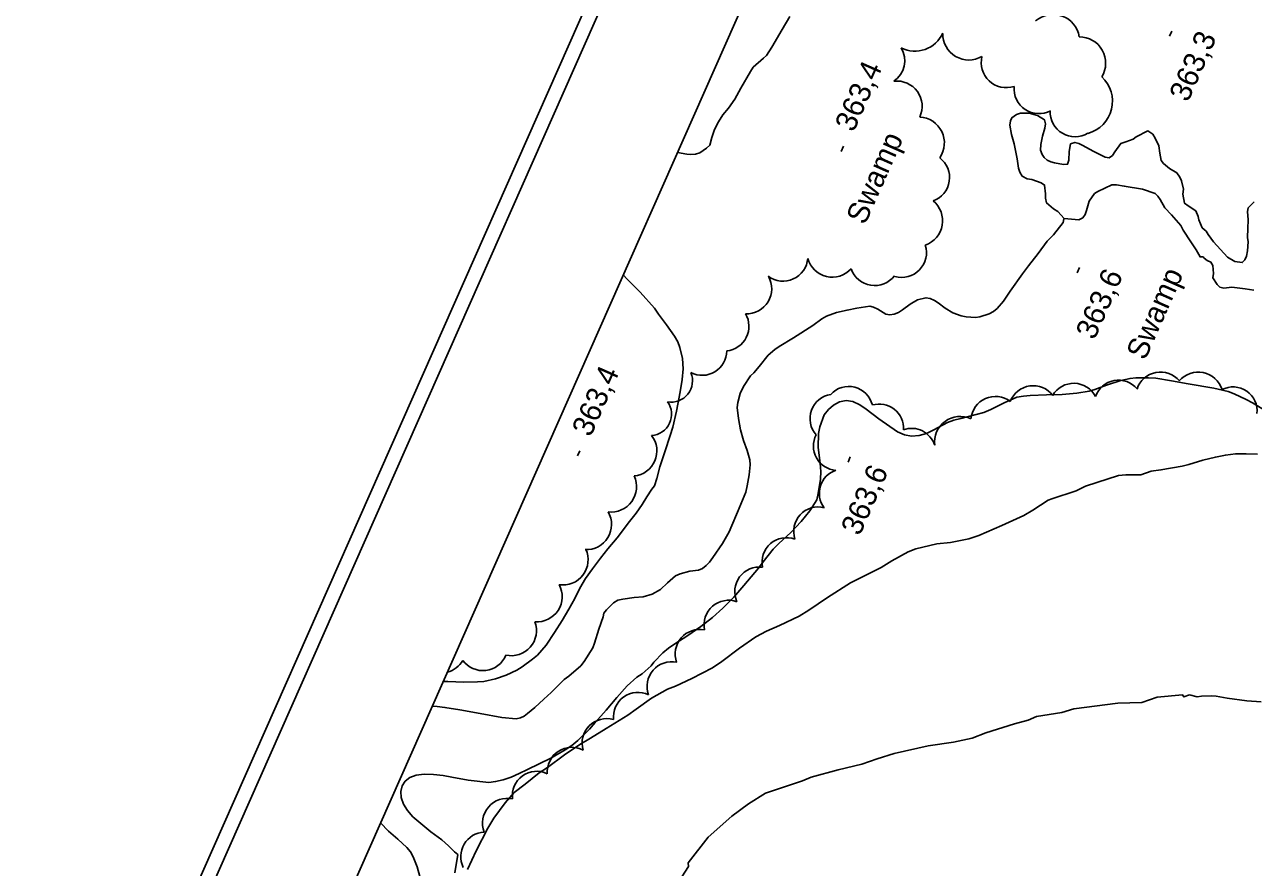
# Model space of a CAD drawing. Extents: x 287698 to 290158, y 5234163 to 5237182.
# Drawn here: x 288054.4 to 288226.3, y 5235640.4 to 5235758.4 of the extents above; entities that cross this region are included whole.
import ezdxf

# ---------------------------------------------------------------- set-up
doc = ezdxf.new("R2010")
doc.units = 0
for name, color, linetype in [('Niveau 2', 7, 'Continuous'), ('Niveau 3', 7, 'Continuous'), ('Niveau 4', 7, 'Continuous'), ('Niveau 44', 7, 'Continuous'), ('Niveau 60', 7, 'Continuous'), ('Niveau 7', 7, 'Continuous')]:
    doc.layers.add(name, color=color, linetype=linetype)

msp = doc.modelspace()

# ---------------------------------------------------------------- linework, layer by layer
at = {"layer": 'Niveau 2'}
for points in [[(288210.56, 5235695.35), (288212.02, 5235695.86), (288213.37, 5235696.06), (288216.33, 5235696.57), (288217.29, 5235696.83), (288219.23, 5235697.4), (288221, 5235697.86), (288222.41, 5235698.13), (288223.82, 5235698.3), (288225.32, 5235698.31), (288226.87, 5235698.26)], [(288179.08, 5235685.01), (288182.04, 5235685.7), (288183.93, 5235685.91), (288186.53, 5235686.4), (288187.93, 5235686.9), (288191.11, 5235688.27), (288194.19, 5235689.69), (288195.48, 5235690.43), (288197.63, 5235691.83), (288198.14, 5235692.02), (288201.54, 5235693.15), (288202.82, 5235693.76), (288204.41, 5235694.28), (288207.46, 5235695.27), (288208.47, 5235695.38), (288210.56, 5235695.35)], [(288116.37, 5235640.14), (288117.59, 5235642.77), (288119.22, 5235645.94), (288120.07, 5235647.3), (288121.66, 5235649.46), (288122.92, 5235650.92), (288124.43, 5235652.06), (288126.4, 5235653.67), (288127.58, 5235654.39), (288129.97, 5235656.18), (288132.08, 5235657.64), (288133.57, 5235658.53), (288135.77, 5235659.88), (288138.82, 5235661.72), (288139.97, 5235662.56), (288142.12, 5235664.13), (288144.38, 5235665.36), (288145.46, 5235665.8), (288147.78, 5235666.89), (288150.64, 5235668.36), (288151.97, 5235669.24), (288154.42, 5235671.1), (288156.71, 5235672.7), (288158.2, 5235673.51), (288160.01, 5235674.27), (288162.76, 5235675.58), (288164.12, 5235676.44), (288166.72, 5235678.2), (288169.96, 5235680.25), (288171.63, 5235681.1), (288174.23, 5235682.41), (288175.76, 5235683.32), (288178.03, 5235684.58), (288179.08, 5235685.01)], [(288201.2, 5235662.6), (288207.37, 5235663.43), (288210.71, 5235663.49), (288212.85, 5235664.26), (288216.42, 5235664.56), (288216.58, 5235664.3), (288217.37, 5235664.56)], [(288217.37, 5235664.56), (288218.47, 5235664.31), (288219.07, 5235664.38), (288220.44, 5235664.46), (288221.13, 5235664.38), (288222.63, 5235664.12), (288225.42, 5235663.76), (288227.4, 5235663.6)], [(288145.43, 5235637.67), (288147.28, 5235640.58), (288147.27, 5235641.05), (288150.06, 5235644.68), (288153.34, 5235647.61), (288155.69, 5235649.32), (288158.05, 5235650.8), (288163.26, 5235652.57), (288164.44, 5235653.06), (288168.23, 5235654.1), (288171.56, 5235654.87), (288173.69, 5235655.63), (288176.05, 5235656.39), (288180.8, 5235657.44), (288184.36, 5235657.98), (288186.97, 5235658.51), (288188.87, 5235659.26), (288192.9, 5235660.53), (288194.8, 5235661.05), (288195.98, 5235661.54), (288199.54, 5235662.09), (288201.2, 5235662.6)]]:
    msp.add_lwpolyline(points, dxfattribs=at)
at = {"layer": 'Niveau 3'}
for p, q in [((288214.58, 5235756.74), (288214.9, 5235757.47)), ((288168.67, 5235740.62), (288168.99, 5235741.35)), ((288201.67, 5235723.65), (288201.99, 5235724.38)), ((288131.77, 5235698.02), (288132.09, 5235698.75)), ((288169.61, 5235697.15), (288169.93, 5235697.88))]:
    msp.add_line(p, q, dxfattribs=at)
at = {"layer": 'Niveau 4'}
for points in [[(288199.83, 5235731.26), (288198.98, 5235732.23), (288198.37, 5235732.61), (288197.38, 5235733.41), (288197.23, 5235734.08), (288197.25, 5235734.7), (288197.1, 5235735.92), (288196.65, 5235736.21), (288195.34, 5235736.69), (288194.65, 5235736.81), (288193.98, 5235737.18), (288193.64, 5235737.74), (288193.48, 5235738.3), (288193.27, 5235739.61), (288192.86, 5235741.67), (288192.5, 5235743), (288192.26, 5235744.32), (288192.33, 5235744.89), (288192.53, 5235745.35), (288193.2, 5235745.81), (288193.75, 5235745.96), (288194.94, 5235745.97), (288196.1, 5235745.66), (288197.08, 5235745.05), (288197.25, 5235744.48), (288197.13, 5235743.88), (288196.8, 5235742.74), (288196.58, 5235741.59), (288196.55, 5235740.82), (288196.75, 5235740.22), (288197.04, 5235739.77), (288197.45, 5235739.42), (288197.96, 5235739.16), (288198.51, 5235739.03), (288199.76, 5235738.81), (288200.32, 5235738.83), (288200.49, 5235739.39), (288200.56, 5235740.63), (288200.74, 5235741.67), (288201.34, 5235741.88), (288201.89, 5235741.74), (288202.37, 5235741.5), (288203.98, 5235740.62), (288205.57, 5235739.83), (288206.14, 5235739.74), (288206.61, 5235740.08), (288206.91, 5235740.58), (288207.75, 5235741.73), (288208.45, 5235741.96), (288209.5, 5235742.33), (288209.94, 5235742.68), (288211.54, 5235743.5), (288212.23, 5235743.02), (288212.58, 5235742.47), (288213.08, 5235741.43), (288213.21, 5235740.37), (288213.41, 5235739.35), (288213.72, 5235738.94), (288214.57, 5235738.24), (288215.59, 5235737.63), (288216.02, 5235737.02), (288216.25, 5235736.5), (288216.56, 5235735.34), (288216.44, 5235734.63), (288216.68, 5235733.37), (288217.18, 5235733.03), (288218.26, 5235732.3), (288218.57, 5235731.54), (288218.67, 5235731.04), (288219.15, 5235729.95), (288219.69, 5235729.47), (288219.99, 5235728.99), (288220.75, 5235727.99)], [(288199.83, 5235731.26), (288200.87, 5235731.13), (288201.92, 5235731.05), (288202.45, 5235731.35), (288202.79, 5235731.8), (288202.97, 5235732.34), (288203.35, 5235733.67), (288204.07, 5235734.73), (288204.56, 5235735.01), (288206.52, 5235735.94), (288207.16, 5235735.94), (288208.25, 5235735.77), (288210.78, 5235735.33), (288212.59, 5235734.73), (288212.97, 5235734.37), (288213.28, 5235733.9), (288213.92, 5235732.75), (288214.88, 5235731.75), (288216.18, 5235730.26), (288216.51, 5235729.61), (288217.56, 5235727.96), (288218.32, 5235726.87), (288218.87, 5235725.86), (288219.27, 5235725.87)], [(288220.75, 5235727.99), (288222.69, 5235725.82), (288223.72, 5235725.22), (288224.75, 5235725.07), (288225.13, 5235725.47), (288225.37, 5235725.96), (288225.5, 5235726.71), (288225.59, 5235727.96), (288225.47, 5235728.59), (288225.52, 5235729.82), (288225.58, 5235731.06), (288225.5, 5235732.2), (288225.6, 5235732.73), (288226.41, 5235733.55)], [(288118.16, 5235661.96), (288121.2, 5235661.43), (288123.19, 5235661.23), (288123.8, 5235661.36), (288124.31, 5235661.61), (288124.78, 5235661.96), (288125.8, 5235662.82), (288127.08, 5235663.96), (288128.07, 5235664.93), (288129.88, 5235666.71), (288130.54, 5235667.21), (288132.23, 5235668.64), (288132.69, 5235669.25), (288133.92, 5235671.17), (288134.15, 5235671.82), (288134.73, 5235673.79), (288135.35, 5235675.51), (288135.47, 5235676.03), (288135.84, 5235676.5), (288136.79, 5235677.46), (288137.42, 5235677.81), (288138.09, 5235677.96), (288139.7, 5235678.22), (288140.96, 5235678.29), (288142.22, 5235678.69), (288143.37, 5235679.34), (288144.36, 5235680.27), (288145.48, 5235681.22), (288146.13, 5235681.53), (288147.49, 5235681.89), (288148.71, 5235682.04), (288149.23, 5235682.28), (288149.76, 5235682.66), (288150.25, 5235683.16), (288150.71, 5235683.78), (288152.04, 5235685.74), (288152.99, 5235687.39), (288153.35, 5235688.27), (288154.17, 5235690.15), (288155.31, 5235692.92), (288155.51, 5235693.82), (288155.79, 5235695.37), (288155.92, 5235696.77), (288155.86, 5235697.47), (288155.51, 5235698.77), (288155.01, 5235700.16), (288154.58, 5235701.67), (288154.27, 5235703.25), (288154.12, 5235704.8), (288154.21, 5235705.5), (288154.53, 5235706.73), (288154.97, 5235707.72), (288155.96, 5235709.21), (288156.43, 5235709.64), (288157.19, 5235710.54), (288158.42, 5235712.1), (288159.36, 5235712.91), (288160, 5235713.32), (288162, 5235714.55), (288164.71, 5235716.26), (288165.93, 5235717.19), (288166.6, 5235717.57), (288168.02, 5235718.1), (288169.47, 5235718.43), (288170.84, 5235718.68), (288172.67, 5235718.95), (288173.16, 5235718.85), (288173.76, 5235718.56), (288174.92, 5235717.85), (288175.46, 5235717.77), (288176.05, 5235717.86), (288176.66, 5235718.09), (288177.25, 5235718.45), (288178.3, 5235719.25), (288179.33, 5235719.87), (288180.51, 5235720.16), (288181.1, 5235720.03), (288181.7, 5235719.78), (288182.24, 5235719.42), (288183.2, 5235718.67), (288184.26, 5235718.04), (288185.46, 5235717.6), (288186.14, 5235717.48), (288187.43, 5235717.37), (288188.07, 5235717.48), (288189.36, 5235717.89), (288189.95, 5235718.21), (288190.48, 5235718.65), (288191.37, 5235719.68), (288192.3, 5235721.06), (288194, 5235723.5), (288194.87, 5235724.6), (288196.19, 5235726.34), (288197.45, 5235728.08), (288198.35, 5235728.96), (288199.72, 5235730.66), (288199.82, 5235731.19), (288199.83, 5235731.26)], [(288226.37, 5235721.19), (288225.15, 5235721.38), (288223.31, 5235721.61), (288222.2, 5235721.51), (288221.64, 5235721.65), (288221.26, 5235722.02), (288220.66, 5235722.95), (288220.73, 5235723.56), (288220.63, 5235724.66), (288220.37, 5235725.15), (288219.86, 5235725.37), (288219.44, 5235725.68), (288219.27, 5235725.87)], [(288111.47, 5235662.99), (288112.15, 5235662.97), (288113.23, 5235662.83), (288115.29, 5235662.47), (288118.16, 5235661.96)], [(288095.96, 5235627.96), (288096.22, 5235628.17), (288097.37, 5235628.94), (288098.63, 5235629.43), (288099.95, 5235629.84), (288101.24, 5235630.44), (288102.45, 5235631.15), (288104.21, 5235632.25), (288106.78, 5235633.7), (288107.96, 5235634.18), (288108.89, 5235634.86), (288109.25, 5235635.35), (288109.5, 5235635.94), (288109.64, 5235636.58), (288109.81, 5235637.85), (288109.69, 5235639.14), (288109.36, 5235640.51), (288108.8, 5235641.92), (288108.4, 5235642.62), (288107.88, 5235643.24), (288106.62, 5235644.38), (288105.31, 5235645.48), (288104.23, 5235646.65)]]:
    msp.add_lwpolyline(points, dxfattribs=at)
at = {"layer": 'Niveau 44'}
for centre, radius, start, end in [((288198.29, 5235756.09), 3.71, 9.1319, 131.0377), ((288178.98, 5235758.91), 4.25, 243.0865, 335.7324), ((288155.42, 5235721.41), 3.51, 267.7766, 29.7187), ((288161.01, 5235683.15), 3.43, 69.8993, 192.0063), ((288118.53, 5235671.44), 3.47, 216.0673, 337.7836), ((288112.63, 5235671.19), 3.58, 285.1602, 329.9842), ((288130.97, 5235653.8), 3.44, 62.5581, 184.2407)]:
    msp.add_arc(centre, radius, start, end, dxfattribs=at)
for centre, major_axis, ratio, start_param, end_param in [((288186.5, 5235757.06), (-1.84, -3.14), 0.999684, 5.217836, 7.346782), ((288201.97, 5235752.99), (3.21, 1.8), 0.999995, 5.222772, 7.347663), ((288174.05, 5235753.33), (3.48, 0.34), 0.999915, 5.217673, 6.720726), ((288191.76, 5235753.07), (-2.41, -2.57), 0.999363, 5.219352, 7.347332), ((288201.95, 5235747.65), (3.92, -2.51), 0.999979, 5.546567, 7.676702), ((288176.44, 5235746.94), (3.15, 1.61), 0.999838, 5.373456, 7.497497), ((288196.31, 5235749.4), (-1.03, -3.33), 0.999964, 4.91995, 7.074728), ((288201.38, 5235746.15), (2.99, -1.79), 0.999985, 3.634031, 5.790747), ((288179.45, 5235741.81), (3.27, 1.6), 0.999028, 5.221263, 7.344981), ((288180.31, 5235736.97), (-2.75, 2.16), 0.999984, 2.590762, 4.72095), ((288179.26, 5235730.92), (-1.25, 3.36), 0.999995, 3.115464, 5.243974), ((288177.11, 5235726.47), (2.42, 2.49), 0.999865, 3.635148, 5.78963), ((288160.52, 5235725.94), (1.44, -3.16), 0.999913, 5.218241, 7.347013), ((288167.42, 5235726.6), (-0.84, -3.47), 0.999672, 5.217124, 7.347727), ((288173.33, 5235725.33), (1.36, -3.2), 0.999815, 4.647474, 6.800559), ((288152.27, 5235716.17), (1.83, 2.96), 0.999866, 3.809409, 5.790913), ((288149.19, 5235712.77), (0.56, 3.43), 0.99979, 2.833753, 4.855644), ((288144.91, 5235708.49), (1.93, 2.26), 0.985538, 3.668732, 5.823756), ((288213.32, 5235706.3), (-0.01, 3.45), 0.999884, 5.410161, 7.533123), ((288218.59, 5235706.24), (0.71, 3.43), 0.99845, 5.220434, 7.343251), ((288169.7, 5235704.32), (-3.31, 0.84), 0.99986, 3.636172, 5.788606), ((288195.51, 5235704.41), (-0.49, 3.4), 0.999445, 5.221066, 7.344974), ((288201.19, 5235704.75), (0.89, 3.31), 0.999928, 5.453361, 7.583214), ((288207.43, 5235705.24), (-2.55, -2.21), 0.999994, 3.115459, 5.24411), ((288223.45, 5235704.27), (1.94, 2.81), 0.988699, 5.21224, 7.362378), ((288167.69, 5235703.25), (-1.68, -2.96), 0.999229, 3.803939, 5.961858), ((288190.22, 5235702.9), (-0.35, -3.42), 0.999984, 2.593726, 4.722036), ((288141.99, 5235703.8), (2.24, 1.94), 0.982453, 4.059022, 6.212145), ((288173.96, 5235701.87), (1.87, 2.85), 0.999476, 5.236788, 7.146135), ((288185.3, 5235699.96), (-1.89, 3.05), 0.999438, 5.296439, 7.427006), ((288178.49, 5235698.47), (-3.35, 0.63), 0.99961, 3.636158, 5.237541), ((288139.35, 5235698.72), (2.98, -1.88), 0.999837, 5.371995, 7.503175), ((288168.17, 5235699.39), (-3.15, -1.3), 0.998607, 5.407663, 7.382232), ((288168.99, 5235692.78), (-2.49, 2.33), 0.99203, 5.789463, 7.673417), ((288136.47, 5235693.72), (2.63, -2.39), 0.999705, 5.33168, 7.455395), ((288165.42, 5235687.47), (-2.32, -2.5), 0.999231, 3.637437, 5.787341), ((288133.02, 5235688.4), (3, 1.83), 0.996766, 4.115, 6.270342), ((288129.74, 5235683.47), (2.13, 2.8), 0.996707, 3.635095, 5.789683), ((288157.2, 5235679.03), (-2.47, 2.39), 0.999762, 5.350625, 7.477865), ((288126.11, 5235678.31), (1.92, 2.95), 0.997129, 3.635451, 5.789327), ((288152.9, 5235674.38), (-2.26, 2.59), 0.999801, 5.217481, 7.348101), ((288122.51, 5235673.57), (2.31, 2.66), 0.996696, 3.637655, 5.787123), ((288148.86, 5235670.3), (-2.61, 2.23), 0.997295, 5.220911, 7.338936), ((288144.93, 5235665.77), (-2.6, 2.25), 0.999862, 5.217454, 7.349618), ((288140.2, 5235661.52), (-2.78, -1.97), 0.999232, 3.637516, 5.787262), ((288135.82, 5235657.85), (-2.4, -2.42), 0.999238, 3.634713, 5.790065), ((288126.06, 5235650.48), (-2.76, -2), 0.999236, 3.635528, 5.78925), ((288121.92, 5235646.64), (-2.26, -2.64), 0.991383, 3.634005, 5.790773), ((288118.9, 5235641.92), (-1.01, -3.32), 0.996314, 3.497966, 5.449621)]:
    msp.add_ellipse(centre, major_axis=major_axis, ratio=ratio, start_param=start_param, end_param=end_param, dxfattribs=at)
at = {"layer": 'Niveau 60'}
for points in [[(289088.15, 5234163.34), (287698.12, 5234778.71), (288762.01, 5237181.96), (290152.07, 5236566.6), (289088.15, 5234163.34)], [(289087.13, 5234165.98), (287700.76, 5234779.73), (288763.06, 5237179.33), (290149.43, 5236565.58), (289087.13, 5234165.98)]]:
    msp.add_lwpolyline(points, dxfattribs=at)
msp.add_lwpolyline([(289077.96, 5234189.73), (287724.51, 5234788.9), (288562.53, 5236681.9), (289915.99, 5236082.74)], close=True, dxfattribs=at)
at = {"layer": 'Niveau 7'}
for points in [[(288161.48, 5235759.51), (288160.39, 5235757.69), (288158.94, 5235755.2), (288158.19, 5235754.03), (288157.78, 5235753.69), (288156.35, 5235752.4), (288155.98, 5235751.81), (288154.6, 5235749.46), (288153.76, 5235747.93), (288152.87, 5235746.69), (288152.1, 5235745.73), (288151.48, 5235744.79), (288150.92, 5235743.69), (288150.57, 5235742.59), (288150.27, 5235741.5), (288149.83, 5235741.08), (288148.89, 5235740.44), (288148.27, 5235740.23), (288147.57, 5235740.18), (288147.07, 5235740.24), (288145.76, 5235740.46)], [(288138.21, 5235723.33), (288138.67, 5235722.79), (288140.53, 5235720.91), (288142.53, 5235718.67), (288143.08, 5235717.85), (288144.23, 5235716.34), (288145.35, 5235714.78), (288145.81, 5235713.96), (288146.1, 5235713.17), (288146.47, 5235711.66), (288146.57, 5235710.22), (288146.41, 5235708.69), (288146.11, 5235706.99), (288145.63, 5235704.26), (288145.11, 5235702.04), (288144.75, 5235700.89), (288143.97, 5235698.59), (288143.3, 5235696.5), (288142.87, 5235694.85), (288142.55, 5235693.82), (288142.17, 5235693.37), (288141.45, 5235692.3), (288140.8, 5235691.22), (288139.97, 5235690.02), (288139.06, 5235688.82), (288137.3, 5235686.56), (288136.03, 5235685), (288134.99, 5235683.72), (288133.87, 5235682.22), (288132.89, 5235680.86), (288132.1, 5235679.52), (288131.4, 5235678.06), (288130.57, 5235676.56), (288129.62, 5235674.97), (288128.57, 5235673.31), (288127.39, 5235671.55), (288126.18, 5235670.15), (288125.48, 5235669.57), (288124.02, 5235668.49), (288123.27, 5235668.05), (288121.78, 5235667.35), (288120.3, 5235666.81), (288118.66, 5235666.46), (288117.79, 5235666.38), (288115.85, 5235666.35), (288113.65, 5235666.44), (288113, 5235666.45)], [(288138.21, 5235723.39), (288138.21, 5235723.33)], [(288145.36, 5235671.72), (288147.18, 5235672.88), (288149, 5235674.16), (288150.64, 5235675.42), (288152.12, 5235676.72), (288153.62, 5235678.25), (288155.05, 5235679.88), (288157.08, 5235682.32), (288157.72, 5235683.21), (288159.15, 5235684.95), (288159.93, 5235685.76), (288161.59, 5235687.29), (288163.07, 5235688.84), (288164.25, 5235690.34), (288165.23, 5235691.85), (288165.44, 5235692.77), (288165.77, 5235694.77), (288165.82, 5235695.84), (288165.73, 5235696.97), (288165.43, 5235699.22), (288165.47, 5235701.15), (288165.65, 5235702.08), (288166.27, 5235703.78), (288166.87, 5235704.51), (288167.6, 5235705.12), (288168.44, 5235705.58), (288169.34, 5235705.77), (288170.29, 5235705.61), (288171.24, 5235705.16), (288172.15, 5235704.54), (288173.91, 5235703.2), (288176.52, 5235701.39), (288177.51, 5235700.97), (288178.5, 5235700.77), (288179.55, 5235700.86), (288180.58, 5235701.17), (288181.61, 5235701.65), (288183.51, 5235702.67), (288184.42, 5235703.02), (288185.38, 5235703.25), (288188.59, 5235704.1), (288189.57, 5235704.52), (288191.43, 5235705.46), (288193.23, 5235706.25), (288194.14, 5235706.4), (288195.11, 5235706.47), (288197.37, 5235706.56), (288199.58, 5235706.59), (288201.6, 5235706.8), (288203.32, 5235707.08), (288204.12, 5235707.31), (288205.78, 5235707.91), (288207.77, 5235708.56), (288209.06, 5235708.85), (288209.85, 5235708.92), (288211.65, 5235708.96), (288212.66, 5235708.88), (288214.86, 5235708.53), (288217.18, 5235708.12), (288220.76, 5235707.49), (288222.77, 5235707.02), (288223.63, 5235706.7), (288225.32, 5235705.93), (288226.19, 5235705.44), (288227.96, 5235704.35)], [(288114.59, 5235639.67), (288115.04, 5235642.22), (288114.54, 5235642.6), (288113.73, 5235643.43), (288112.79, 5235644.29), (288111.26, 5235645.42), (288108.72, 5235647.52), (288108, 5235648.39), (288107.44, 5235649.29), (288107.12, 5235650.2), (288107.07, 5235651.07), (288107.26, 5235651.85), (288107.67, 5235652.5), (288108.3, 5235653.03), (288109.18, 5235653.34), (288110.33, 5235653.47), (288111.64, 5235653.44), (288112.98, 5235653.27), (288114.21, 5235653.05), (288116.46, 5235652.66), (288119.35, 5235652.33), (288120.31, 5235652.45), (288121.36, 5235652.7), (288122.48, 5235653.07), (288123.63, 5235653.55), (288124.78, 5235654.12), (288128.04, 5235655.73), (288130.05, 5235656.89), (288130.96, 5235657.5), (288131.81, 5235658.2), (288133.45, 5235659.79), (288134.26, 5235660.69), (288135.79, 5235662.45), (288137.29, 5235664.23), (288138.71, 5235665.84), (288140.07, 5235667.06), (288140.79, 5235667.54), (288142.07, 5235668.63), (288142.45, 5235669.16), (288143.69, 5235670.47), (288144.48, 5235671.11), (288145.36, 5235671.72)]]:
    msp.add_lwpolyline(points, dxfattribs=at)

# ---------------------------------------------------------------- texts
at = {"layer": 'Niveau 3'}
for s, p in [('363,3', (288217.16, 5235747.4)), ('363,4', (288170.39, 5235743.2)), ('363,6', (288204.08, 5235714.13)), ('363,4', (288133.6, 5235700.55)), ('363,6', (288171.24, 5235686.71))]:
    msp.add_text(s, height=3, rotation=66.1217, dxfattribs=at).set_placement(p)
at = {"layer": 'Niveau 7'}
for p in [(288171.98, 5235730.22), (288211.16, 5235711.26)]:
    msp.add_text('Swamp', height=3, rotation=66.1212, dxfattribs=at).set_placement(p)

doc.saveas('drawing.dxf')
